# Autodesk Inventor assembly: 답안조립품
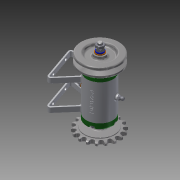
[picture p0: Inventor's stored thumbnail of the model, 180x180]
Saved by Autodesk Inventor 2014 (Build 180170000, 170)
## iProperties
Created: 2016-03
Part Number: 답안조립품
Document SubType Name: Assembly
Designer: SEC
Author: SEC
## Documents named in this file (16)
- C:\Documents and Settings\SEC\바탕 화면\460307V1022\답안조립품.iam
- C:\Documents and Settings\SEC\바탕 화면\460307V1022\본체.ipt
- C:\Documents and Settings\SEC\바탕 화면\460307V1022\V벨트풀리.ipt
- C:\Documents and Settings\SEC\바탕 화면\460307V1022\너트 M 8.ipt
- C:\Documents and Settings\SEC\바탕 화면\460307V1022\니플 M 6 x 0.75.ipt
- C:\Documents and Settings\SEC\바탕 화면\460307V1022\베어링 15 x 32 x 9.ipt
- C:\Documents and Settings\SEC\바탕 화면\460307V1022\볼트 M4 x 12.ipt
- C:\Documents and Settings\SEC\바탕 화면\460307V1022\볼트 M 6 x 8.ipt
- C:\Documents and Settings\SEC\바탕 화면\460307V1022\스프로킷.ipt
- C:\Documents and Settings\SEC\바탕 화면\460307V1022\스프링와셔 8.ipt
- C:\Documents and Settings\SEC\바탕 화면\460307V1022\오일 실 15 25 7.ipt
- C:\Documents and Settings\SEC\바탕 화면\460307V1022\와셔 6x11.5.ipt
- C:\Documents and Settings\SEC\바탕 화면\460307V1022\와셔 8x17.ipt
- C:\Documents and Settings\SEC\바탕 화면\460307V1022\축.ipt
- C:\Documents and Settings\SEC\바탕 화면\460307V1022\커버.ipt
- C:\Documents and Settings\SEC\바탕 화면\460307V1022\키 3 x 3 x 12.ipt
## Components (11 placed, 3 different names)
1. V벨트풀리:1
2. KS B 2023 6002 - 15 x 32 x 9:1
3. KS B 2023 6002 - 15 x 32 x 9:2
4. ISO 4762 M4 x 12:3
5. ISO 4762 M4 x 12:4
6. ISO 4762 M4 x 12:5
7. ISO 4762 M4 x 12:6
8. ISO 4762 M4 x 12:1
9. ISO 4762 M4 x 12:7
10. ISO 4762 M4 x 12:8
11. ISO 4762 M4 x 12:9
